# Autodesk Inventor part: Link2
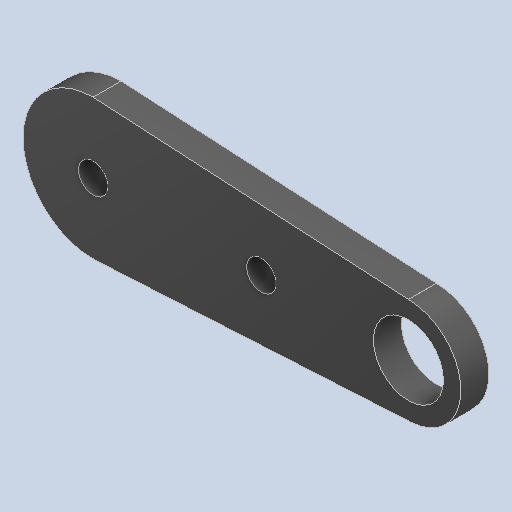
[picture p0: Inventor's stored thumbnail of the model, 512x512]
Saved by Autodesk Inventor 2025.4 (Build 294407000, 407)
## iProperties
Created: 2026-09
Part Number: Link2
Material: Generic
Document SubType Name: Modeling
Designer: AdminForWorker
Density: 1 g/cm^3
Appearance: Default
Title: Link2 v9 v1
Author: AdminForWorker
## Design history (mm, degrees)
feature "Body1"
body "Solid1"
